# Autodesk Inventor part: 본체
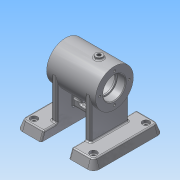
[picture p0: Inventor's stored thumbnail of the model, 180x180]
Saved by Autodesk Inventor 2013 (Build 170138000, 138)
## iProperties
Created: 2016-07
Part Number: 본체
Material: 알루미늄 6061
Document SubType Name: Modeling
Designer: Administrator
Density: 2.71 g/cm^3
Mass: 499.755 g
Surface Area: 541.889 cm^2
Volume: 184.411 cm^3
Author: Administrator
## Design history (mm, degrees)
sketch "스케치1"
  geometry: L1 (0, 0)-(0, 70); L2 (0, 70)-(70, 70); L3 (0, 87)-(0, 97); L4 (0, 97)-(70, 97); L5 (70, 97)-(70, 87); L6 (1, 86)-(11.7, 86); L7 (12, 85.7)-(12, 84); L8 (12, 84)-(14, 84); L9 (14, 84)-(14, 89); L10 (17, 92)-(53, 92); L11 (56, 89)-(56, 84); L12 (56, 84)-(58, 84); L13 (58, 84)-(58, 85.7); L14 (58.3, 86)-(69, 86); L15 (69, 86)-(70, 87); L16 (1, 86)-(0, 87); A1 r 0.3 centre (11.7, 85.7) between (12, 85.7) and (11.7, 86); A2 r 0.3 centre (58.3, 85.7) between (58.3, 86) and (58, 85.7); A3 r 3 centre (53, 89) between (56, 89) and (53, 92); A4 r 3 centre (17, 89) between (17, 92) and (14, 89); 7 further points
  constraints: 32 end point, 16 point on line, 8 point on circle, 8 tangent, 7 perpendicular, 6 parallel, 4 centre point, 2 equal radius, 1 vertical
  dimensions: "d0" = 70 distance of L1.start L1.end; "d1" = 70 distance of L1.end L2.end; "d2" = 54 diameter of L4 L2; "d3" = 12 distance of point (0, 86) point (12, 86); "d4" = 2 distance of L7.end L8.end; "d5" = 42 distance of point (14, 92) point (56, 92); "d6" = 2 distance of L11.end L12.end; "d7" = 32 diameter of L6 L2; "d8" = 28 diameter of L8 L2; "d9" = 44 diameter of L10 L2; "d10" = 28 diameter of L12 L2; "d11" = 32 diameter of L14 L2; "d12" = 0.3 radius of A1; "d13" = 3 radius of A3; "d14" = 1 distance of L14.end point (70, 86); "d15" = 1 distance of L5.end point (70, 86) (= d14); "d16" = 1 distance of L6.start point (0, 86) (= d14); "d17" = 1 distance of L3.start point (0, 86) (= d16)
revolve "회전1" sketch "스케치1" stored, may be unused: angle "d18" = 90 deg
node "작업 평면1"
sketch "스케치2"
  geometry: L1 (0, 27)-(0, -27) reference; L2 (0, 0)-(-22, 0); C1 r 5 at (-22, 0)
  constraints: 2 end point, 1 centre point, 1 coincident, 1 perpendicular
  dimensions: "d21" = 22 distance of L2.start L2.end; "d22" = 10 diameter of C1
extrude "돌출1" join sketch "스케치2" stored distance "d23" = 10; taper "d24" = 0 deg
sketch "스케치3"
  geometry: L1 (-90, 0)-(-90, -50); L2 (20, -50)-(20, 50); L3 (-90, 50)-(-90, 0); L4 (20, 50)-(-15, 50); L5 (-15, 50)-(-15, -50); L6 (20, -50)-(-15, -50); L7 (-90, -50)-(-55, -50); L8 (-55, -50)-(-55, 50); L9 (-55, 50)-(-90, 50); L10 (-55, 0)-(-15, 0); 1 further point
  constraints: 20 end point, 4 perpendicular, 2 equal length, 2 midpoint
  dimensions: "d27" = 50 distance of L1.start L1.end; "d29" = 100 distance of L2.start L2.end; "d31" = 35 distance of L2.end L4.end; "d33" = 35 distance of L1.end L7.end; "d34" = 100 distance of L7.end L8.end
extrude "돌출2" join sketch "스케치3" distance "d35" = 12; taper "d36" = 0 deg
sketch "스케치5"
  geometry: L1 (-15, 50)-(-15, -50) reference; L2 (-15, 0)-(-7, 0); L3 (-7, 0)-(-7, 27); L4 (-7, 27)-(-15, 27); L5 (-15, 27)-(-15, -27); L6 (-15, -27)-(-7, -27); L7 (-7, -27)-(-7, 27); 1 further point
  constraints: 12 end point, 3 perpendicular, 2 parallel, 1 horizontal, 1 midpoint, 1 point on line
  dimensions: "d41" = 8 distance of L2.start L2.end; "d42" = 27 distance of L2.end L3.end; "d43" = 54 distance of L6.end L3.end
extrude "돌출3" join sketch "스케치5" stored distance "d44" = 12; taper "d45" = 0 deg
node "작업 평면2"
sketch "스케치6"
  geometry: L1 (0, 0)-(6, 0); L2 (0, 0)-(25.441, -15.898); L3 (25.441, -15.898)-(22.262, -20.986); L4 (25.441, -15.898)-(21.133, -13.206); L5 (22.262, -20.986)-(19.145, -19.038); A1 r 27 centre (0, 0) between (19.145, -19.038) and (22.897, -14.308); 1 further point
  constraints: 10 end point, 2 point on circle, 2 point on line, 1 centre point, 1 coincident, 1 horizontal, 1 parallel, 1 perpendicular
  dimensions: "d48" = 30 distance of L1.start L2.end; "d49" = 32 deg angle of L1 L2
revolve "회전2" sketch "스케치6" stored, may be unused: angle "d52" = 90 deg
node "작업 평면3"
sketch "스케치7"
  geometry: 2 further points
  constraints: 1 other
feature "엠보싱1" sketch "스케치7" dims "d0" = 70, "d1" = 70, "d2" = 54, "d3" = 12, "d4" = 2, "d5" = 42, "d6" = 2, "d7" = 32, "d8" = 28, "d9" = 44, "d10" = 28, "d11" = 32, "d12" = 0.3, "d13" = 3, "d14" = 1, "d15" = 1 (= d14), "d16" = 1 (= d14), "d17" = 1 (= d16), "d54" = 0.5, "d55" = 0
sketch "스케치8"
  geometry: L1 (0, 43)-(70, 43) reference; L2 (55, 12)-(55, 70) reference; L3 (55, 43)-(55, 22); L4 (15, 12)-(15, 70) reference; L5 (55, 22)-(15, 22); L6 (15, 22)-(15, 43); L7 (15, 43)-(55, 43); 1 further point
  constraints: 8 end point, 5 point on line, 1 perpendicular
  dimensions: "d57" = 21 distance of L3.start L3.end; "d58" = 21 distance of L5.end L6.end
extrude "돌출4" join sketch "스케치8" stored distance "d59" = 8; taper "d60" = 0 deg
sketch "스케치9"
  geometry: L1 (-55, 0)-(-90, 0) reference; L2 (-35, -32)-(-23.5, -32); L3 (-23.5, -32)-(-23.5, -32); L4 (-27, -28.5)-(-43, -28.5); L5 (-46.5, -32)-(-46.5, -32); L6 (-43, -35.5)-(-27, -35.5); L7 (-23.5, -32)-(-23.5, -32); A1 r 3.5 centre (-43, -32) between (-43, -28.5) and (-46.5, -32); A2 r 3.5 centre (-43, -32) between (-46.5, -32) and (-43, -35.5); A3 r 3.5 centre (-27, -32) between (-27, -35.5) and (-23.5, -32); A4 r 3.5 centre (-27, -32) between (-23.5, -32) and (-27, -28.5); 5 further points
  constraints: 12 end point, 8 point on circle, 8 point on line, 8 tangent, 4 centre point, 3 equal radius, 3 perpendicular, 1 parallel
  dimensions: "d62" = 11.5 distance of L2.start L2.end; "d63" = 3.5 distance of L2.end point (-23.5, -28.5); "d64" = 23 distance of point (-23.5, -28.5) point (-46.5, -28.5); "d65" = 7 distance of point (-46.5, -28.5) point (-46.5, -35.5); "d66" = 23 distance of point (-46.5, -35.5) point (-23.5, -35.5); "d67" = 3.5 radius of A1
extrude "돌출5" cut sketch "스케치9" stored distance "d68" = 8; taper "d69" = 0 deg
feature "면 기울기1" dims angle "d70" = -20 deg
feature "면 기울기2" dims angle "d71" = 20 deg
feature "면 기울기3" dims angle "d72" = -20 deg
sketch "스케치10"
  geometry: C1 r 17 at (0, 0) reference; A1 r 21 centre (0, 0) between (0, 21) and (21, 0); 3 further points
  constraints: 4 point on circle, 1 centre point, 1 coincident
  dimensions: "d73" = 42 diameter of A1
hole "구멍1" sketch "스케치10" at (0, 21), (21, 0), (0, -21), (-21, 0) diameter "d74" = 3.242; stored, may be unused: countersink angle "d78" = 90 deg, drill point angle "d80" = 118 deg; dims "d75" = 8, "d76" = 4, "d77" = 2, "d79" = 10
sketch "스케치11"
  geometry: C1 r 5 at (0, 0) reference; 2 further points
  constraints: 1 coincident
hole "구멍2" sketch "스케치11" at (0, 0) diameter "d81" = 5.188; stored, may be unused: countersink angle "d85" = 90 deg, drill point angle "d87" = 118 deg; dims "d82" = 20, "d83" = 4, "d84" = 2, "d86" = 30
sketch "스케치12"
  geometry: C1 r 6 at (0, 0) reference; 2 further points
  constraints: 1 coincident
hole "구멍3" sketch "스케치12" at (0, 0) diameter "d88" = 5.188; stored, may be unused: countersink angle "d92" = 90 deg, drill point angle "d94" = 118 deg; dims "d89" = 20, "d90" = 4, "d91" = 2, "d93" = 30
sketch "스케치13"
  geometry: L1 (15.632, -45.632)-(15.632, 45.632) reference; L2 (15.632, 45.632)-(-15, 45.632) reference; L3 (20, -50)-(20, 50) reference; L4 (20, 50)-(-15, 50) reference; L5 (20, 50)-(7.5, 50); L6 (7.5, 50)-(7.5, 37.5); L7 (15.632, 0)-(6, 0); 3 further points
  constraints: 6 end point, 2 perpendicular, 1 coincident, 1 midpoint, 1 point on line, 1 symmetric about line
  dimensions: "d95" = 12.5 distance of L3.end L5.end; "d96" = 12.5 distance of L5.end L6.end
hole "구멍4" sketch "스케치13" at (7.5, 37.5), (7.5, -37.5) diameter "d97" = 6; stored, may be unused: countersink angle "d101" = 90 deg, drill point angle "d103" = 118 deg; dims "d98" = 20, "d99" = 10, "d100" = 4, "d102" = 30
fillet "모깎기1" dims "d104" = 10, "d105" = 5
fillet "모깎기2" dims "d106" = 10, "d107" = 5
fillet "모깎기3" dims "d108" = 10, "d109" = 5
fillet "모깎기4" dims "d110" = 10, "d111" = 5
sketch "스케치14"
  geometry: L1 (-40, 0)-(0, 0) reference; L2 (0, 4)-(0, 0) reference; L3 (-40, 4)-(0, 4) reference; L4 (-40, 0)-(-40, 4) reference; 1 further point
extrude "돌출6" join sketch "스케치14" stored distance "d112" = 8; taper "d113" = 0 deg
fillet "모깎기5" dims "d114" = 2
sketch "스케치15"
  geometry: L1 (40, 0)-(0, 0) reference; L2 (40, 4)-(40, 0) reference; L3 (0, 4)-(40, 4) reference; L4 (0, 0)-(0, 4) reference; 1 further point
extrude "돌출7" join sketch "스케치15" stored distance "d115" = 8; taper "d116" = 0 deg
fillet "모깎기6" dims "d117" = 2
fillet "모깎기7" dims "d118" = 2
fillet "모깎기8" dims "d119" = 2
fillet "모깎기9" dims "d120" = 2
fillet "모깎기10" dims "d121" = 2
fillet "모깎기11" dims "d122" = 2
node "솔리드1"
mirror "대칭1"
mirror "대칭2"
mirror "대칭3"
other parameters: "d46" = -35, "d53" = 27
